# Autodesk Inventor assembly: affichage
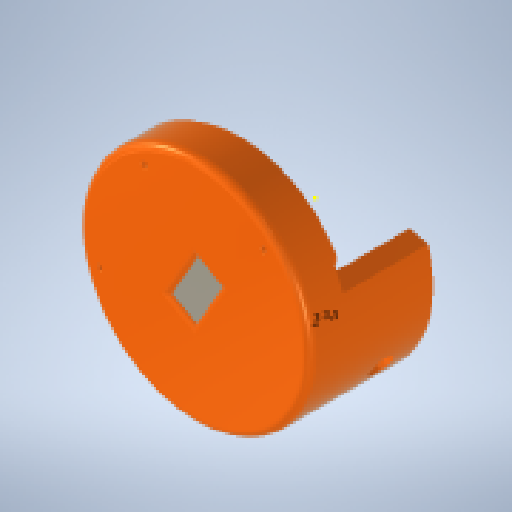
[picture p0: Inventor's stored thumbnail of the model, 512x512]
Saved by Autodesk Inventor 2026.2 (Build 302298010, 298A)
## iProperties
Created: 2026-09
Part Number: affichage
Document SubType Name: Assembly
Designer: mel
Author: mel
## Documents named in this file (3)
- D:\travail\année 2026-2027\1 sti2d IT\poubelle à verre\affichage.iam
- D:\travail\année 2026-2027\1 sti2d IT\poubelle à verre\1-3-inch-4pin-white-oled-lcd-display-12864-iic-i2c-interface-module-for-arduino-1.snapshot.1\Geekcreit 1.3 Inch 4Pin\Geekcreit 1.3 Inch 4Pin\Geekcreit 1.3 .iam
- D:\travail\année 2026-2027\1 sti2d IT\poubelle à verre\Affichage.ipt
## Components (2 placed, 2 different names)
1. Geekcreit 1.3 :1 [sub-assembly] — Placage:2, Placage:3
2. Affichage:1 — Placage:2, Placage:3
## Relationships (2: Mate 2)
- Placage:2 [Mate]: Geekcreit 1.3 :1 ↔ Affichage:1
- Placage:3 [Mate]: Geekcreit 1.3 :1 ↔ Affichage:1
